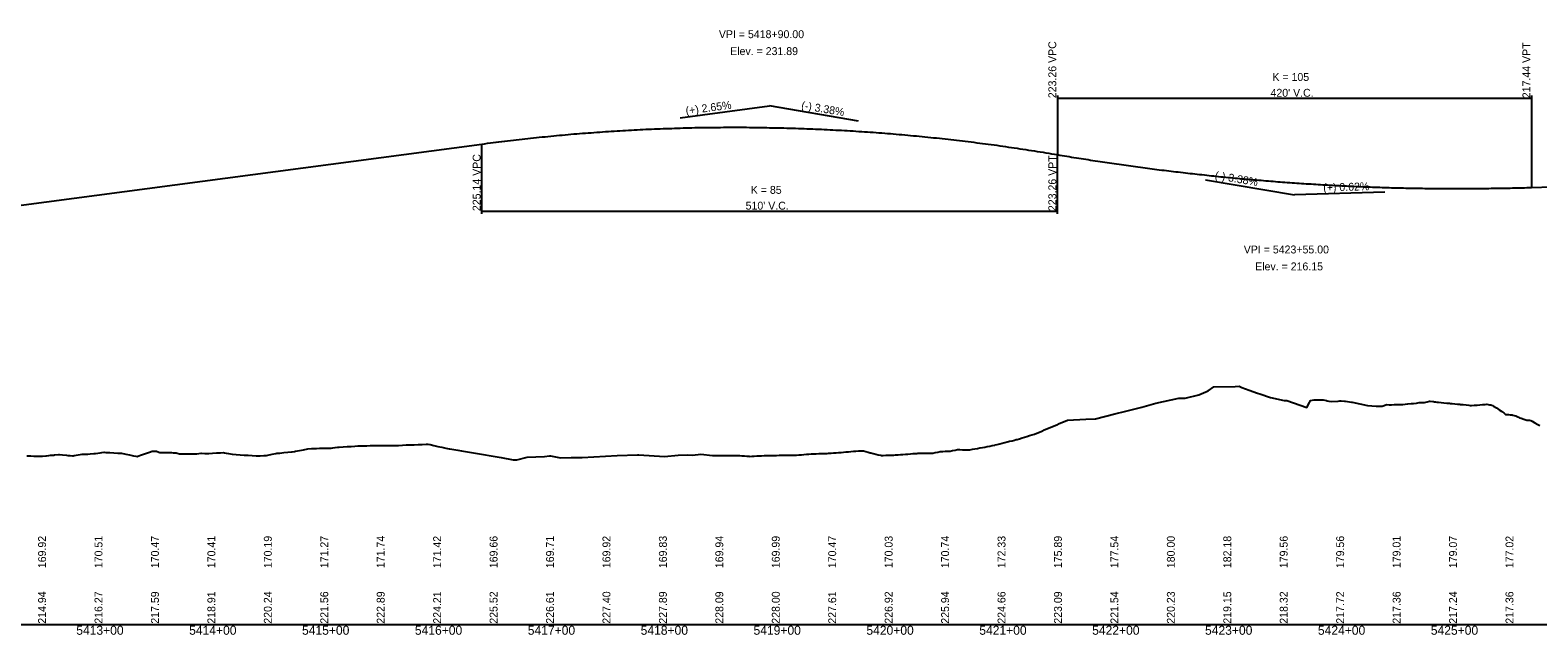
# Model space of a CAD drawing. Extents: x 1876258 to 1932803, y 754739 to 837911.
# Drawn here: x 1879217 to 1880552, y 775980 to 776516 of the extents above; entities that cross this region are included whole.
import ezdxf

# ---------------------------------------------------------------- set-up
doc = ezdxf.new("R2010")
doc.units = 0
for name, color, linetype in [('RD_DDB_GradeTX', 7, 'Continuous'), ('RD_DDB_Profile_EX', 7, 'Continuous'), ('RD_DDB_Profile_Lbl', 7, 'Continuous'), ('RD_DDB_Profile_PR', 7, 'Continuous'), ('RD_DDB_StaTX', 7, 'Continuous'), ('RD_DDB_StripGrade', 7, 'Continuous'), ('RD_DDB_VCLbl', 7, 'Continuous'), ('RD_GPK_Profile_Cell', 7, 'Continuous')]:
    doc.layers.add(name, color=color, linetype=linetype)

msp = doc.modelspace()

# ---------------------------------------------------------------- linework, layer by layer
at = {"layer": 'RD_DDB_GradeTX'}
for p, q in [((1879792.3, 776438.1), (1879871.6, 776448.6)), ((1879950.5, 776435.2), (1879871.6, 776448.6)), ((1880257.7, 776383.2), (1880336.6, 776369.9)), ((1880416.6, 776372.3), (1880336.6, 776369.9))]:
    msp.add_line(p, q, dxfattribs=at)
at = {"layer": 'RD_DDB_Profile_EX'}
for points in [[(1880051.3, 776144.4), (1880053.5, 776144.8), (1880055.7, 776145.2), (1880057.9, 776145.6), (1880060.1, 776146), (1880062.3, 776146.4), (1880064.5, 776146.8), (1880066.7, 776147.3), (1880068.9, 776147.7), (1880071.1, 776148.1), (1880071.4, 776148.2), (1880073.3, 776148.7), (1880075.5, 776149.2), (1880077.7, 776149.8), (1880079.9, 776150.3), (1880082.1, 776150.9), (1880083.2, 776151.2), (1880084.3, 776151.5), (1880086.5, 776152), (1880088.7, 776152.6), (1880090.1, 776153), (1880090.9, 776153.2), (1880093.1, 776153.8), (1880095.3, 776154.5), (1880097.5, 776155.2), (1880099.6, 776155.8), (1880101.8, 776156.5), (1880104, 776157.2), (1880106.2, 776157.9), (1880108.4, 776158.8), (1880110.6, 776159.7), (1880112.8, 776160.6), (1880115, 776161.5), (1880117.2, 776162.4), (1880119.4, 776163.3), (1880121.6, 776164.2), (1880123.8, 776165.2), (1880126, 776166.1), (1880128.2, 776167.1), (1880130.4, 776168), (1880135.6, 776170.3), (1880151.7, 776171), (1880160.4, 776171.3), (1880177.5, 776175.8), (1880187.2, 776178.2), (1880201.4, 776181.6), (1880213.9, 776185.2), (1880234.3, 776189.7), (1880239.8, 776189.8), (1880251.8, 776192.5), (1880260.2, 776196.3), (1880265.3, 776199.6), (1880284.2, 776200.1), (1880287.5, 776200.2), (1880290, 776199.1), (1880296.5, 776196.9), (1880303.8, 776194.1), (1880306, 776193.4), (1880315.5, 776190.2), (1880327.6, 776187.7), (1880329.9, 776187.5), (1880347.6, 776181.4), (1880349.9, 776185.7), (1880350.9, 776187.6), (1880354, 776188.3), (1880358.4, 776188.3), (1880362, 776188.2), (1880363.5, 776188), (1880365, 776187.7), (1880365.7, 776187.2), (1880367.1, 776186.9), (1880369.8, 776186.8), (1880375.3, 776187.1), (1880376.7, 776187.3), (1880378.1, 776187.2), (1880381, 776187.1), (1880381.9, 776186.9), (1880387.2, 776186.1), (1880387.6, 776186), (1880401.4, 776183.2), (1880409, 776182.5), (1880410.5, 776182.6), (1880411.6, 776182.6), (1880414.3, 776182.6), (1880418.4, 776184), (1880420.6, 776183.8), (1880422.6, 776183.9), (1880425, 776184), (1880425.7, 776184), (1880427.4, 776184.1), (1880429, 776184.1), (1880429.9, 776184.1), (1880432.3, 776184.2), (1880432.7, 776184.2), (1880434.8, 776184.4), (1880436.8, 776184.6), (1880437.2, 776184.6), (1880439.9, 776184.9), (1880442.1, 776185.1), (1880444.6, 776185.4), (1880447, 776185.7)], [(1880447, 776185.7), (1880448.2, 776185.8), (1880449.5, 776185.8), (1880451.3, 776185.8), (1880451.9, 776185.9), (1880454.3, 776186.5), (1880456.2, 776187), (1880456.8, 776187), (1880459.2, 776186.8), (1880459.7, 776186.8), (1880460.6, 776186.5), (1880461.7, 776186.3), (1880462.6, 776186.1), (1880464.1, 776186), (1880466.6, 776185.8), (1880469, 776185.6), (1880471.5, 776185.4), (1880473.9, 776185.2), (1880475, 776185.1), (1880476.4, 776185), (1880478.8, 776184.8), (1880481.2, 776184.5), (1880483.2, 776184.4), (1880483.7, 776184.2), (1880484.2, 776184.1), (1880485.7, 776184.1), (1880486.1, 776184), (1880488.6, 776183.7), (1880491, 776183.4), (1880492.3, 776183.3), (1880493.5, 776183.3), (1880495.9, 776183.4), (1880496.6, 776183.4), (1880498.4, 776183.6), (1880500.8, 776183.8), (1880503.3, 776184), (1880505.7, 776184.2), (1880506.9, 776184.3), (1880508.1, 776184.1), (1880509.5, 776183.9), (1880510.6, 776183.7), (1880512.1, 776183.3), (1880513, 776182.7), (1880515.5, 776181), (1880517.9, 776179.4), (1880520.4, 776177.8), (1880522.2, 776176.6), (1880522.8, 776176), (1880523.6, 776175.3), (1880525.3, 776175.2), (1880526.3, 776175.1), (1880527.7, 776175), (1880529.6, 776174.8), (1880530.2, 776174.6), (1880531.3, 776174.3), (1880532.7, 776174.1), (1880535, 776172.9), (1880536, 776172.4), (1880537.5, 776171.9), (1880539.9, 776171.1), (1880542.4, 776170.3), (1880544.8, 776170.1), (1880545.9, 776170), (1880547.3, 776169.2), (1880549.7, 776167.8), (1880552.2, 776166.4), (1880553.9, 776165.5)], [(1879213.6, 776138.7), (1879217.1, 776138.6), (1879219.8, 776138.4), (1879220.6, 776138.4), (1879224.1, 776138.2), (1879224.4, 776138.2), (1879227.6, 776138.4), (1879230.5, 776138.7), (1879231.1, 776138.7), (1879233.1, 776138.9), (1879234.6, 776139.1), (1879237.4, 776139.3), (1879238.1, 776139.4), (1879241.6, 776139.7), (1879242.6, 776139.8), (1879245.1, 776139.5), (1879248.6, 776139.1), (1879250, 776139), (1879252.1, 776138.8), (1879254.2, 776138.6), (1879254.6, 776138.7), (1879255.6, 776138.8), (1879259.1, 776139.4), (1879262.6, 776140), (1879263.4, 776140.1), (1879266.1, 776140.2), (1879267.7, 776140.2), (1879269.6, 776140.4), (1879273.1, 776140.7), (1879274.5, 776140.8), (1879276.6, 776141.1), (1879278.5, 776141.4), (1879280.1, 776141.5), (1879282.1, 776141.8), (1879283.6, 776141.7), (1879286.1, 776141.5), (1879287.1, 776141.5), (1879290.6, 776141.3), (1879294.1, 776141.1), (1879295.4, 776141), (1879297.3, 776140.9), (1879297.6, 776140.9), (1879301.2, 776140.1), (1879304.7, 776139.4), (1879308.2, 776138.6), (1879310.3, 776138.2), (1879311.3, 776138.1), (1879311.9, 776138.4), (1879315.2, 776139.5), (1879318.7, 776140.7), (1879322.2, 776141.8), (1879324.5, 776142.6), (1879325.7, 776142.6), (1879328.7, 776142.6), (1879329.2, 776142.4), (1879331.5, 776141.5), (1879332.7, 776141.5), (1879336.2, 776141.5), (1879339.7, 776141.5), (1879341.8, 776141.5), (1879343.2, 776141.4), (1879345.8, 776141.3), (1879346.7, 776141), (1879348.9, 776140.4), (1879350.2, 776140.4), (1879353.7, 776140.4), (1879357.2, 776140.3), (1879360.7, 776140.3), (1879362.3, 776140.3), (1879364.2, 776140.5), (1879367.7, 776140.9), (1879368.3, 776140.9), (1879371.2, 776140.7), (1879372.8, 776140.6), (1879374.7, 776140.7), (1879378.2, 776141), (1879381.7, 776141.2), (1879385.2, 776141.4), (1879387.7, 776141.6), (1879388.7, 776141.4), (1879390.3, 776141.1), (1879392.2, 776140.7), (1879395.4, 776140.1), (1879395.7, 776140.1), (1879399.2, 776139.8), (1879402.7, 776139.5), (1879406.2, 776139.3), (1879407, 776139.2), (1879409.7, 776139.1), (1879413.2, 776138.8), (1879416.7, 776138.6), (1879417.5, 776138.6), (1879419.8, 776138.5), (1879420.2, 776138.6), (1879423.7, 776138.9), (1879425.9, 776139), (1879427.2, 776139.3), (1879430.9, 776140), (1879434.2, 776140.7)], [(1879434.2, 776140.7), (1879435.2, 776140.9), (1879437.7, 776141.1), (1879441.2, 776141.5), (1879444.7, 776141.8), (1879448.2, 776142.1), (1879448.6, 776142.1), (1879450.7, 776142.3), (1879451.7, 776142.6), (1879455.2, 776143.3), (1879458.7, 776144), (1879462.4, 776144.8), (1879465.8, 776145), (1879469.3, 776145.2), (1879470.3, 776145.2), (1879472.8, 776145.3), (1879474.2, 776145.3), (1879476.3, 776145.4), (1879479.8, 776145.4), (1879483.3, 776145.5), (1879484.8, 776145.6), (1879486.8, 776145.9), (1879489.2, 776146.2), (1879490.3, 776146.3), (1879493.8, 776146.5), (1879497.3, 776146.8), (1879500.8, 776147), (1879504.3, 776147.3), (1879506.9, 776147.4), (1879507.8, 776147.5), (1879510.7, 776147.6), (1879511.3, 776147.6), (1879514.8, 776147.6), (1879517.9, 776147.7), (1879518.3, 776147.7), (1879521.8, 776147.7), (1879525.3, 776147.8), (1879528.8, 776147.8), (1879532.3, 776147.8), (1879535.8, 776147.9), (1879536.6, 776147.9), (1879538.5, 776147.8), (1879539.3, 776147.8), (1879539.9, 776147.8), (1879542.8, 776147.9), (1879546.3, 776148), (1879549.8, 776148.2), (1879553.3, 776148.3), (1879556.8, 776148.4), (1879560.3, 776148.5), (1879563.8, 776148.6), (1879567.3, 776148.8), (1879569.2, 776148.8), (1879570.8, 776148.5), (1879574.3, 776147.8), (1879577.8, 776147), (1879581.3, 776146.3), (1879584.8, 776145.5), (1879587.8, 776144.9), (1879588.3, 776144.8), (1879591.8, 776144.2), (1879595.3, 776143.7), (1879598.8, 776143.1), (1879602.3, 776142.5), (1879605.8, 776141.9), (1879609.3, 776141.3), (1879633.8, 776137), (1879644.4, 776135), (1879647.7, 776135), (1879656.8, 776137.4), (1879672.3, 776138), (1879676.6, 776138.5), (1879677.4, 776138.5), (1879685, 776137.1), (1879686.3, 776136.8), (1879695.9, 776137), (1879703.9, 776137.1), (1879705.6, 776137.2), (1879736.6, 776139), (1879754.6, 776139.6), (1879755.1, 776139.6), (1879755.7, 776139.5), (1879778.4, 776137.9), (1879790.5, 776139.3), (1879799, 776139.5), (1879803.2, 776139.2), (1879810.6, 776140), (1879821.1, 776139), (1879822.6, 776138.9), (1879826, 776138.8), (1879845.4, 776138.9), (1879847.1, 776138.7), (1879849.3, 776138.5), (1879851.5, 776138.3), (1879853.7, 776138.2), (1879854.1, 776138.1), (1879855.9, 776138.2), (1879858, 776138.3), (1879860.2, 776138.5), (1879862.4, 776138.6), (1879864.6, 776138.7)], [(1879864.6, 776138.7), (1879866.8, 776138.8), (1879867.7, 776138.9), (1879869, 776138.9), (1879871.2, 776138.9), (1879873.4, 776139), (1879875.6, 776139), (1879877.8, 776139), (1879880, 776139.1), (1879882.2, 776139.1), (1879884.4, 776139.1), (1879886.6, 776139.2), (1879887.8, 776139.2), (1879888.8, 776139.2), (1879890, 776139.2), (1879891, 776139.2), (1879893.2, 776139.2), (1879893.9, 776139.2), (1879895.4, 776139.3), (1879897.6, 776139.5), (1879899.8, 776139.6), (1879902, 776139.8), (1879904.2, 776140), (1879906.4, 776140.1), (1879908.6, 776140.3), (1879910.1, 776140.4), (1879910.8, 776140.4), (1879913, 776140.5), (1879915.2, 776140.6), (1879917.4, 776140.6), (1879919.5, 776140.7), (1879921.7, 776140.8), (1879922.5, 776140.8), (1879923.9, 776140.9), (1879926.1, 776141.1), (1879928.3, 776141.2), (1879930.5, 776141.4), (1879932.7, 776141.6), (1879934.9, 776141.7), (1879937.1, 776141.9), (1879939.3, 776142.1), (1879941.5, 776142.2), (1879943.7, 776142.4), (1879945.9, 776142.6), (1879948.1, 776142.8), (1879950.3, 776143), (1879950.9, 776143), (1879952.5, 776143), (1879954.9, 776143.1), (1879956.9, 776142.5), (1879959.1, 776141.8), (1879960.8, 776141.3), (1879961.3, 776141.2), (1879963.5, 776140.7), (1879965.7, 776140.2), (1879967.9, 776139.6), (1879970.1, 776139.1), (1879970.8, 776138.9), (1879972.3, 776139), (1879974.5, 776139.1), (1879976.7, 776139.1), (1879978.8, 776139.2), (1879981, 776139.3), (1879981.6, 776139.3), (1879983.2, 776139.4), (1879985.4, 776139.6), (1879987.6, 776139.7), (1879989.8, 776139.9), (1879992, 776140.1), (1879993.3, 776140.2), (1879994.2, 776140.2), (1879996.4, 776140.4), (1879998.6, 776140.6), (1880000.8, 776140.7), (1880002.1, 776140.8), (1880003, 776140.9), (1880005.2, 776140.9), (1880007.4, 776140.9), (1880009.6, 776140.9), (1880011.8, 776141), (1880014, 776141), (1880016.2, 776141.1), (1880018.4, 776141.5), (1880020.6, 776141.9), (1880022.8, 776142.3), (1880023.7, 776142.4), (1880025, 776142.5), (1880027.2, 776142.6), (1880029.4, 776142.7), (1880031.6, 776142.8), (1880033.8, 776143.2), (1880036, 776143.6), (1880038.2, 776144.1), (1880038.5, 776144.1), (1880040.3, 776144.1), (1880042.5, 776144), (1880044.7, 776143.9), (1880045.1, 776143.9), (1880046.9, 776144), (1880049.1, 776144), (1880051.3, 776144.4)]]:
    msp.add_lwpolyline(points, dxfattribs=at)
at = {"layer": 'RD_DDB_Profile_PR'}
for p, q in [((1878881.6, 776317.5), (1879616.6, 776414.8)), ((1880126.6, 776405.4), (1880126.6, 776405.4)), ((1880546.6, 776376.3), (1880861.6, 776386.1))]:
    msp.add_line(p, q, dxfattribs=at)
for points in [[(1879616.6, 776414.8), (1879626.8, 776416.1), (1879637, 776417.4), (1879647.2, 776418.6), (1879657.4, 776419.7), (1879667.6, 776420.8), (1879677.8, 776421.8), (1879688, 776422.8), (1879698.2, 776423.7), (1879708.4, 776424.5), (1879718.6, 776425.2), (1879728.8, 776426), (1879739, 776426.6), (1879749.2, 776427.2), (1879759.4, 776427.7), (1879769.6, 776428.2), (1879779.8, 776428.5), (1879790, 776428.9), (1879800.2, 776429.2), (1879810.4, 776429.4), (1879820.6, 776429.5), (1879830.8, 776429.6), (1879841, 776429.6), (1879851.2, 776429.6), (1879861.4, 776429.5), (1879871.6, 776429.3), (1879881.8, 776429.1), (1879892, 776428.8), (1879902.2, 776428.5), (1879912.4, 776428.1), (1879922.6, 776427.6), (1879932.8, 776427.1), (1879943, 776426.5), (1879953.2, 776425.9), (1879963.4, 776425.2), (1879973.6, 776424.4), (1879983.8, 776423.6), (1879994, 776422.7), (1880004.2, 776421.7), (1880014.4, 776420.7), (1880024.6, 776419.6), (1880034.8, 776418.5), (1880045, 776417.3), (1880055.2, 776416), (1880065.4, 776414.7), (1880075.6, 776413.3), (1880085.8, 776411.8), (1880096, 776410.3), (1880106.2, 776408.7), (1880116.4, 776407.1), (1880126.6, 776405.4)], [(1880126.6, 776405.4), (1880135, 776404), (1880143.4, 776402.6), (1880151.8, 776401.3), (1880160.2, 776400), (1880168.6, 776398.7), (1880177, 776397.5), (1880185.4, 776396.3), (1880193.8, 776395.1), (1880202.2, 776394), (1880210.6, 776392.9), (1880219, 776391.8), (1880227.4, 776390.8), (1880235.8, 776389.8), (1880244.2, 776388.8), (1880252.6, 776387.9), (1880261, 776387), (1880269.4, 776386.1), (1880277.8, 776385.3), (1880286.2, 776384.5), (1880294.6, 776383.7), (1880303, 776383), (1880311.4, 776382.3), (1880319.8, 776381.6), (1880328.2, 776381), (1880336.6, 776380.4), (1880345, 776379.8), (1880353.4, 776379.3), (1880361.8, 776378.8), (1880370.2, 776378.3), (1880378.6, 776377.9), (1880387, 776377.5), (1880395.4, 776377.1), (1880403.8, 776376.8), (1880412.2, 776376.5), (1880420.6, 776376.2), (1880429, 776376), (1880437.4, 776375.8), (1880445.8, 776375.7), (1880454.2, 776375.5), (1880462.6, 776375.4), (1880471, 776375.4), (1880479.4, 776375.4), (1880487.8, 776375.4), (1880496.2, 776375.4), (1880504.6, 776375.5), (1880513, 776375.6), (1880521.4, 776375.7), (1880529.8, 776375.9), (1880538.2, 776376.1), (1880546.6, 776376.3)]]:
    msp.add_spline(points, degree=3, dxfattribs=at)
at = {"layer": 'RD_DDB_VCLbl'}
for p, q in [((1880126.6, 776457.9), (1880126.6, 776405.4)), ((1880126.6, 776455.4), (1880546.6, 776455.4)), ((1880546.6, 776457.9), (1880546.6, 776376.3)), ((1879616.6, 776352.9), (1879616.6, 776414.8)), ((1880126.6, 776352.9), (1880126.6, 776405.4)), ((1879616.6, 776355.4), (1880126.6, 776355.4))]:
    msp.add_line(p, q, dxfattribs=at)
at = {"layer": 'RD_GPK_Profile_Cell'}
msp.add_line((1877681.6, 775989.1), (1883481.6, 775989.1), dxfattribs=at)

# ---------------------------------------------------------------- texts
at = {"layer": 'RD_DDB_GradeTX'}
for s, rotation, p in [('(+) 2.65%', 7.5405, (1879797.7, 776440.8)), ('(-) 3.38%', 350.3942, (1879899.3, 776445.9)), ('(-) 3.38%', 350.3942, (1880265.7, 776383.9)), ('(+) 0.62%', 1.7643, (1880362.2, 776372.7))]:
    msp.add_text(s, height=7, rotation=rotation, dxfattribs=at).set_placement(p)
at = {"layer": 'RD_DDB_Profile_Lbl'}
for s, p in [('VPI = 5418+90.00', (1879826.7, 776508.6)), ('Elev. = 231.89', (1879836.7, 776493.6)), ('VPI = 5423+55.00', (1880291.7, 776317.9)), ('Elev. = 216.15', (1880301.8, 776302.9))]:
    msp.add_text(s, height=7, dxfattribs=at).set_placement(p)
at = {"layer": 'RD_DDB_StaTX'}
for s, p in [('5413+00', (1879257.4, 775980.1)), ('5414+00', (1879357.4, 775980.1)), ('5415+00', (1879457.4, 775980.1)), ('5416+00', (1879557.4, 775980.1)), ('5417+00', (1879657.4, 775980.1)), ('5418+00', (1879757.4, 775980.1)), ('5419+00', (1879857.4, 775980.1)), ('5420+00', (1879957.4, 775980.1)), ('5421+00', (1880057.4, 775980.1)), ('5422+00', (1880157.4, 775980.1)), ('5423+00', (1880257.4, 775980.1)), ('5424+00', (1880357.4, 775980.1)), ('5425+00', (1880457.4, 775980.1))]:
    msp.add_text(s, height=8, dxfattribs=at).set_placement(p)
at = {"layer": 'RD_DDB_StripGrade'}
for s, p in [('223.26 VPC', (1880125.6, 776455.4)), ('217.44 VPT', (1880545.6, 776455.4)), ('225.14 VPC', (1879615.6, 776355.4)), ('223.26 VPT', (1880125.6, 776355.4)), ('169.92', (1879230.6, 776039.1)), ('170.51', (1879280.6, 776039.1)), ('170.47', (1879330.6, 776039.1)), ('170.41', (1879380.6, 776039.1)), ('170.19', (1879430.6, 776039.1)), ('171.27', (1879480.6, 776039.1)), ('171.74', (1879530.6, 776039.1)), ('171.42', (1879580.6, 776039.1)), ('169.66', (1879630.6, 776039.1)), ('169.71', (1879680.6, 776039.1)), ('169.92', (1879730.6, 776039.1)), ('169.83', (1879780.6, 776039.1)), ('169.94', (1879830.6, 776039.1)), ('169.99', (1879880.6, 776039.1)), ('170.47', (1879930.6, 776039.1)), ('170.03', (1879980.6, 776039.1)), ('170.74', (1880030.6, 776039.1)), ('172.33', (1880080.6, 776039.1)), ('175.89', (1880130.6, 776039.1)), ('177.54', (1880180.6, 776039.1)), ('180.00', (1880230.6, 776039.1)), ('182.18', (1880280.6, 776039.1)), ('179.56', (1880330.6, 776039.1)), ('179.56', (1880380.6, 776039.1)), ('179.01', (1880430.6, 776039.1)), ('179.07', (1880480.6, 776039.1)), ('177.02', (1880530.6, 776039.1)), ('214.94', (1879230.6, 775989.9)), ('216.27', (1879280.6, 775989.9)), ('217.59', (1879330.6, 775989.9)), ('218.91', (1879380.6, 775989.9)), ('220.24', (1879430.6, 775989.9)), ('221.56', (1879480.6, 775989.9)), ('222.89', (1879530.6, 775989.9)), ('224.21', (1879580.6, 775989.9)), ('225.52', (1879630.6, 775989.9)), ('226.61', (1879680.6, 775989.9)), ('227.40', (1879730.6, 775989.9)), ('227.89', (1879780.6, 775989.9)), ('228.09', (1879830.6, 775989.9)), ('228.00', (1879880.6, 775989.9)), ('227.61', (1879930.6, 775989.9)), ('226.92', (1879980.6, 775989.9)), ('225.94', (1880030.6, 775989.9)), ('224.66', (1880080.6, 775989.9)), ('223.09', (1880130.6, 775989.9)), ('221.54', (1880180.6, 775989.9)), ('220.23', (1880230.6, 775989.9)), ('219.15', (1880280.6, 775989.9)), ('218.32', (1880330.6, 775989.9)), ('217.72', (1880380.6, 775989.9)), ('217.36', (1880430.6, 775989.9)), ('217.24', (1880480.6, 775989.9)), ('217.36', (1880530.6, 775989.9))]:
    msp.add_text(s, height=7, rotation=90, dxfattribs=at).set_placement(p)
at = {"layer": 'RD_DDB_VCLbl'}
for s, p in [('K = 105', (1880317.1, 776470.7)), ("420' V.C.", (1880315.4, 776456.7)), ('K = 85', (1879855, 776370.7)), ("510' V.C.", (1879850.4, 776356.7))]:
    msp.add_text(s, height=7, dxfattribs=at).set_placement(p)

doc.saveas('drawing.dxf')
